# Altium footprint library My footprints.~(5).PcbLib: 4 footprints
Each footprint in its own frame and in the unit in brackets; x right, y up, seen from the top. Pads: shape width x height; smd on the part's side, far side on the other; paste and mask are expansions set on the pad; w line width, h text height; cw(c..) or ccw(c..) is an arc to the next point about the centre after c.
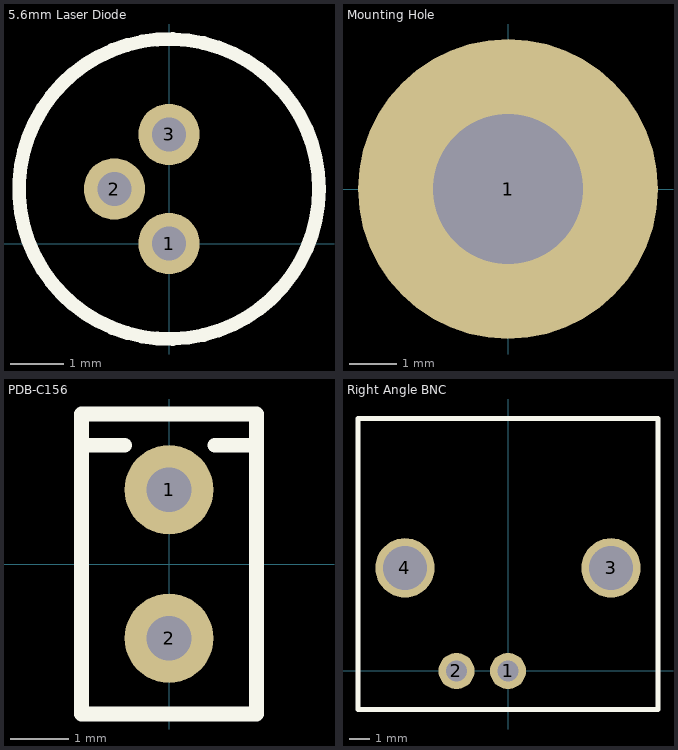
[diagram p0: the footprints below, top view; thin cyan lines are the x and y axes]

## 5.6mm Laser Diode [mil] "5.6mm Laser Diode"
pads (3):
  round 45 hole 25: 1(0,0) 2(-40,40) 3(0,80)
Top Overlay:
  circle w10: c0,40 r110
3D body: height 137.8, standoff -255.91, extent -108.77,-70.1 109,148.1

## Mounting Hole [mil]
pads (1):
  round 250 hole 125: 1(0,0)

## PDB-C156 [mil] "Photodiode"
height 291
pads (2):
  round 60 hole 30: 1(0,50) 2(0,-50)
Top Overlay:
  lines w10: -59,80 -30,80 ; 31,80 59,80 ; -59,-101 -59,101 59,101 59,-101 -59,-101

## Right Angle BNC [mil]
pads (4):
  round 70 hole 40: 1(0,0) 2(-100,0)
  round 115 hole 85: 3(200,200) 4(-200,200)
Top Overlay:
  lines w10: -291,-75 -291,490 291,490 291,-75 -291,-75
M5 Assembly Top:
  text ".Designator" at -160,-140 h40
3D body: height 519.2, standoff -161.8, extent -290.5,-50 290.5,1325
